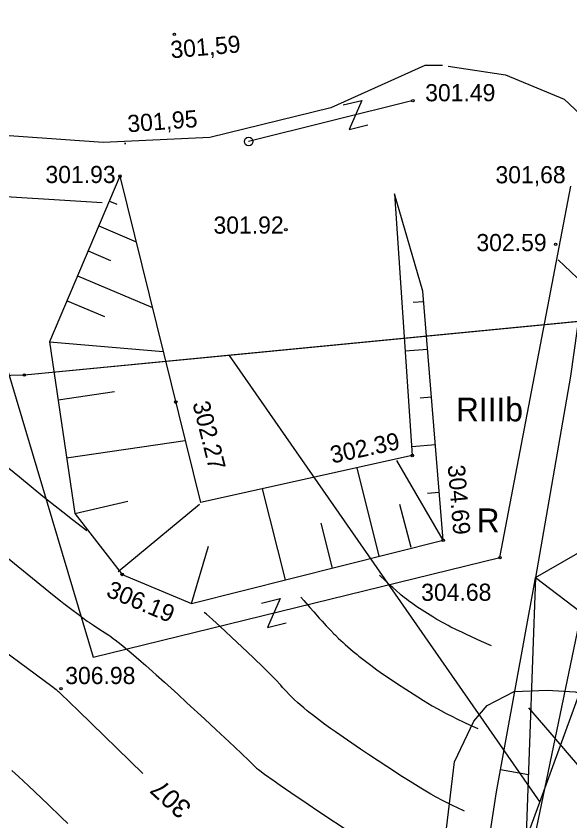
# Model space of a CAD drawing. Extents: x 7477803 to 7478145, y 5500698 to 5500984.
# Drawn here: x 7478004.34 to 7478026.29, y 5500777.55 to 5500809.46 of the extents above; entities that cross this region are included whole.
import ezdxf

# ---------------------------------------------------------------- set-up
doc = ezdxf.new("R2010")
doc.units = 0
for name, color, linetype in [('203-Punkt załamania granicy działki nie stabilizowany', 7, 'Continuous'), ('e_Proj', 7, 'Continuous'), ('gr_dzialki', 7, 'Continuous'), ('gr_klasy', 7, 'Continuous'), ('jezdnia', 7, 'Continuous'), ('kraweznik', 7, 'Continuous'), ('ogr_symb', 7, 'Continuous'), ('ogr_w_skali', 7, 'Continuous'), ('opis_klasy', 7, 'Continuous'), ('opis_uzytek', 7, 'Continuous'), ('pkt_wys', 7, 'Continuous'), ('przehaczenie', 7, 'Continuous'), ('skarp_wypel', 7, 'Continuous'), ('skarpa_gora', 7, 'Continuous'), ('t', 7, 'Continuous'), ('warst_ciagla', 7, 'Continuous'), ('warst_opis', 7, 'Continuous'), ('warst_pogrub', 7, 'Continuous'), ('warst_przeryw', 7, 'Continuous')]:
    doc.layers.add(name, color=color, linetype=linetype)

# ---------------------------------------------------------------- blocks, each defined once
blk = doc.blocks.new('203')
blk.add_circle((0, 0), 0.045)
blk = doc.blocks.new('140')
at = {"layer": 'pkt_wys'}
blk.add_circle((0, 0), 0.045, dxfattribs=at)
blk.add_circle((0, 0), 0.045, dxfattribs=at)
blk = doc.blocks.new('801')
at = {"layer": 'pkt_wys'}
blk.add_circle((0, 0), 0.045, dxfattribs=at)
blk.add_circle((0, 0), 0.045, dxfattribs=at)
blk = doc.blocks.new('POINT_DISPLAY')
blk.add_line((0, 0), (0, 0))
blk = doc.blocks.new('801_5_1')
at = {"layer": 'pkt_wys'}
blk.add_circle((0, 0), 0.05, dxfattribs=at)
blk.add_circle((0, 0), 0.05, dxfattribs=at)
blk = doc.blocks.new('991_5_1')
at = {"layer": 'przehaczenie'}
blk.add_lwpolyline([(-0.38, 0.5), (0.38, 0.5), (-0.38, -0.5), (0.38, -0.5)], dxfattribs=at)
blk = doc.blocks.new('801_5_3')
at = {"layer": 'pkt_wys'}
blk.add_circle((0, 0), 0.05, dxfattribs=at)
blk.add_circle((0, 0), 0.05, dxfattribs=at)

msp = doc.modelspace()

# ---------------------------------------------------------------- linework, layer by layer
at = {"layer": 'e_Proj'}
msp.add_lwpolyline([(7478085.721, 5500828.46), (7478062.59, 5500828.394), (7478057.723, 5500828.457), (7478045.093, 5500816.16), (7478029.949, 5500801.309), (7478024.948, 5500777.245), (7478020.357, 5500757.697), (7478013.921, 5500735.554), (7478010.536, 5500720.256)], dxfattribs=at)
at = {"layer": 'gr_dzialki'}
for points in [[(7478036.02, 5500798.26), (7478004.67, 5500795.23)], [(7478004.67, 5500795.23), (7477980.59, 5500794.64)]]:
    msp.add_lwpolyline(points, dxfattribs=at)
at = {"layer": 'gr_klasy'}
for points in [[(7478030.37, 5500797.71), (7478012.78, 5500796.01)], [(7478012.78, 5500796.01), (7478004.67, 5500795.23)], [(7478012.78, 5500796.01), (7478025.09, 5500778.3)], [(7478004.67, 5500795.23), (7477980.59, 5500794.64)], [(7478025.09, 5500778.3), (7478028.63, 5500788.01)], [(7478019.23, 5500762.35), (7478025.09, 5500778.3)]]:
    msp.add_lwpolyline(points, dxfattribs=at)
at = {"layer": 'jezdnia'}
for points in [[(7478007.787, 5500804.444), (7477996.226, 5500805.272), (7477980.454, 5500806.765), (7477965.783, 5500808.078), (7477950.842, 5500809.092), (7477941.412, 5500809.312), (7477933.642, 5500808.883), (7477925.833, 5500807.985), (7477921.044, 5500806.84), (7477908.409, 5500802.106), (7477902.302, 5500799.559), (7477897.005, 5500796.683), (7477891.579, 5500793.077), (7477886.813, 5500789.372), (7477881.349, 5500784.496), (7477881.326, 5500784.471)], [(7478021.234, 5500807.499), (7478020.534, 5500807.508), (7478016.815, 5500805.824), (7478012.017, 5500804.649), (7478007.787, 5500804.444)]]:
    msp.add_lwpolyline(points, dxfattribs=at)
at = {"layer": 'kraweznik'}
msp.add_lwpolyline([(7478021.467, 5500807.475), (7478023.732, 5500807.128), (7478026.054, 5500806.173), (7478027.956, 5500804.381), (7478029.354, 5500802.427), (7478030.248, 5500801.153), (7478031.021, 5500799.823), (7478031.916, 5500797.559), (7478032.259, 5500795.246), (7478031.695, 5500792.194), (7478036.74, 5500790.972)], dxfattribs=at)
at = {"layer": 'ogr_symb'}
for points in [[(7478020.018, 5500806.096), (7478013.557, 5500804.491)], [(7478023.515, 5500787.992), (7478026.319, 5500802.715)], [(7478003.756, 5500796.28), (7478007.399, 5500784.044), (7478023.515, 5500787.992)]]:
    msp.add_lwpolyline(points, dxfattribs=at)
at = {"layer": 'ogr_w_skali'}
msp.add_circle((7478013.557, 5500804.491), 0.17, dxfattribs=at)
msp.add_circle((7478013.557, 5500804.491), 0.17, dxfattribs=at)
at = {"layer": 'pkt_wys'}
msp.add_lwpolyline([(7478008.633, 5500804.409), (7478008.685, 5500804.407)], dxfattribs=at)
msp.add_lwpolyline([(7478008.633, 5500804.409), (7478008.685, 5500804.407)], dxfattribs=at)
msp.add_arc((7478008.657, 5500804.365), 0.05, 56.1028, 119.1086, dxfattribs=at)
msp.add_arc((7478008.657, 5500804.365), 0.05, 56.1028, 119.1086, dxfattribs=at)
at = {"layer": 'skarp_wypel'}
for p, q in [((7478008.039, 5500802.128), (7478008.334, 5500802.002)), ((7478007.619, 5500801.14), (7478009.101, 5500800.511)), ((7478007.2, 5500800.153), (7478008.086, 5500799.776)), ((7478006.78, 5500799.166), (7478009.743, 5500797.907)), ((7478006.361, 5500798.178), (7478007.838, 5500797.551)), ((7478020.488, 5500798.136), (7478020.074, 5500798.102)), ((7478005.666, 5500796.542), (7478010.174, 5500796.162)), ((7478020.643, 5500796.245), (7478019.761, 5500796.172)), ((7478006.003, 5500794.242), (7478008.243, 5500794.571)), ((7478020.798, 5500794.353), (7478020.357, 5500794.317)), ((7478006.34, 5500791.942), (7478011.044, 5500792.633)), ((7478020.954, 5500792.462), (7478020.017, 5500792.385)), ((7478021.264, 5500788.679), (7478019.429, 5500791.846)), ((7478018.733, 5500788.044), (7478017.853, 5500791.551)), ((7478015.015, 5500787.111), (7478014.109, 5500790.719)), ((7478021.109, 5500790.571), (7478020.639, 5500790.532)), ((7478024.924, 5500787.202), (7478030.818, 5500790.618)), ((7478006.663, 5500789.743), (7478008.775, 5500790.232)), ((7478008.383, 5500787.443), (7478011.606, 5500790.11)), ((7478019.995, 5500788.392), (7478019.546, 5500790.098)), ((7478016.874, 5500787.577), (7478016.428, 5500789.353)), ((7478011.297, 5500786.178), (7478011.961, 5500788.446)), ((7478023.537, 5500779.595), (7478024.639, 5500779.393))]:
    msp.add_line(p, q, dxfattribs=at)
at = {"layer": 'skarpa_gora'}
msp.add_line((7478008.458, 5500803.115), (7478011.651, 5500790.173), dxfattribs=at)
for points in [[(7478007.749, 5500802.055), (7477980.618, 5500803.745), (7477949.546, 5500805.521), (7477933.975, 5500805.774), (7477921.168, 5500803.47), (7477908.381, 5500800.266), (7477897.978, 5500794.654), (7477888.325, 5500787.474), (7477883.93, 5500782.828)], [(7478008.458, 5500803.115), (7478005.666, 5500796.542), (7478006.663, 5500789.743), (7478008.546, 5500787.325), (7478011.297, 5500786.178), (7478021.264, 5500788.679), (7478020.453, 5500798.558), (7478019.339, 5500802.417)], [(7478019.339, 5500802.417), (7478020.04, 5500792.038), (7478011.651, 5500790.173)], [(7478025.82, 5500799.793), (7478026.819, 5500798.852), (7478026.304, 5500795.183), (7478024.924, 5500787.202), (7478034.104, 5500780.215), (7478036.041, 5500775.672), (7478038.759, 5500769.132)], [(7478008.529, 5500720.966), (7478013.614, 5500738.374), (7478016.556, 5500749.806), (7478020.275, 5500763.382), (7478022.118, 5500770.559), (7478023.375, 5500778.71), (7478024.881, 5500786.965)], [(7478024.881, 5500786.965), (7478024.924, 5500787.202), (7478024.325, 5500770.813), (7478019.007, 5500749.589), (7478017.956, 5500746.211), (7478015.629, 5500736.387), (7478013.818, 5500729.802), (7478010.366, 5500720.316)]]:
    msp.add_lwpolyline(points, dxfattribs=at)
at = {"layer": 't'}
msp.add_lwpolyline([(7478013.952, 5500749.22), (7478016.25, 5500756.094), (7478018.043, 5500762.466), (7478020.822, 5500772.519), (7478021.714, 5500779.89), (7478022.482, 5500781.51), (7478023.011, 5500782.131), (7478024.071, 5500782.682), (7478025.381, 5500782.734), (7478026.491, 5500782.665), (7478029.072, 5500781.778), (7478030.398, 5500780.809)], dxfattribs=at)
at = {"layer": 'warst_ciagla'}
for points in [[(7478007.15, 5500789.054), (7478006.579, 5500789.493), (7478006.188, 5500789.799), (7478005.406, 5500790.421), (7478004.472, 5500791.175), (7478003.267, 5500792.155), (7478002.666, 5500792.64), (7478002.125, 5500793.072), (7478001.851, 5500793.289), (7478001.432, 5500793.613), (7478001.005, 5500793.938), (7478000.786, 5500794.101), (7478000.34, 5500794.426), (7478000.112, 5500794.589), (7477999.761, 5500794.833)], [(7478001.984, 5500785.687), (7478004.486, 5500783.837), (7478005.76, 5500782.892), (7478005.923, 5500782.769), (7478005.988, 5500782.716), (7478006.025, 5500782.684), (7478006.105, 5500782.608), (7478006.816, 5500781.917), (7478009.361, 5500779.436)], [(7478022.103, 5500777.945), (7478021.829, 5500778.069), (7478021.663, 5500778.147), (7478021.366, 5500778.292), (7478021.232, 5500778.361), (7478020.989, 5500778.49), (7478020.772, 5500778.613), (7478020.637, 5500778.692), (7478020.38, 5500778.847), (7478019.951, 5500779.115), (7478019.657, 5500779.302), (7478019.031, 5500779.707), (7478018.339, 5500780.163), (7478017.986, 5500780.4), (7478017.472, 5500780.75), (7478017, 5500781.079), (7478016.806, 5500781.218), (7478016.561, 5500781.395), (7478016.445, 5500781.481), (7478016.2, 5500781.666), (7478016.085, 5500781.755), (7478015.94, 5500781.869), (7478015.871, 5500781.924), (7478015.74, 5500782.032), (7478015.58, 5500782.167), (7478015.507, 5500782.232), (7478015.356, 5500782.37), (7478015.289, 5500782.435), (7478015.166, 5500782.559), (7478015.053, 5500782.68), (7478014.904, 5500782.845), (7478014.825, 5500782.931), (7478014.627, 5500783.142), (7478014.317, 5500783.46), (7478014.141, 5500783.634), (7478013.742, 5500784.024), (7478013.506, 5500784.25), (7478013.086, 5500784.646), (7478012.428, 5500785.257), (7478012.123, 5500785.535), (7478011.883, 5500785.748), (7478011.798, 5500785.82)], [(7478024.645, 5500782.041), (7478025.489, 5500781.057), (7478026.336, 5500780.074), (7478027.186, 5500779.094), (7478028.037, 5500778.115)]]:
    msp.add_lwpolyline(points, dxfattribs=at)
at = {"layer": 'warst_pogrub'}
msp.add_lwpolyline([(7478023.182, 5500784.49), (7478022.789, 5500784.667), (7478022.183, 5500784.944), (7478022.027, 5500785.017), (7478021.77, 5500785.141), (7478021.572, 5500785.24), (7478021.465, 5500785.296), (7478021.285, 5500785.394), (7478021.018, 5500785.545), (7478020.853, 5500785.642), (7478020.746, 5500785.706), (7478020.537, 5500785.836), (7478020.327, 5500785.971), (7478020.22, 5500786.043), (7478020.058, 5500786.155), (7478019.892, 5500786.277), (7478019.807, 5500786.342), (7478019.722, 5500786.409), (7478019.606, 5500786.504), (7478019.547, 5500786.554), (7478019.427, 5500786.656), (7478019.265, 5500786.801), (7478019.182, 5500786.877), (7478018.993, 5500787.056), (7478018.746, 5500787.301)], dxfattribs=at)
at = {"layer": 'warst_przeryw'}
for points in [[(7478003.413, 5500788.456), (7478005.133, 5500787.052), (7478005.637, 5500786.645), (7478005.845, 5500786.48), (7478006.107, 5500786.273), (7478006.232, 5500786.175), (7478006.496, 5500785.971), (7478006.85, 5500785.704), (7478006.991, 5500785.6), (7478007.164, 5500785.475), (7478007.244, 5500785.419), (7478007.408, 5500785.308), (7478007.618, 5500785.174), (7478007.875, 5500785.011), (7478008.016, 5500784.915), (7478008.094, 5500784.86), (7478008.206, 5500784.777), (7478008.265, 5500784.732), (7478008.391, 5500784.634), (7478008.574, 5500784.488), (7478008.671, 5500784.408), (7478008.906, 5500784.213), (7478009.297, 5500783.877), (7478009.487, 5500783.712), (7478009.753, 5500783.476), (7478009.893, 5500783.351), (7478010.223, 5500783.055), (7478010.751, 5500782.573), (7478011.112, 5500782.241), (7478011.806, 5500781.599), (7478012.267, 5500781.17), (7478012.788, 5500780.683), (7478013.009, 5500780.476), (7478013.289, 5500780.211), (7478013.569, 5500779.943), (7478013.669, 5500779.845), (7478013.807, 5500779.709), (7478013.869, 5500779.651), (7478013.946, 5500779.588), (7478013.993, 5500779.55), (7478014.186, 5500779.406), (7478014.563, 5500779.138), (7478014.803, 5500778.971), (7478015.227, 5500778.681), (7478015.911, 5500778.218), (7478016.304, 5500777.954), (7478017.624, 5500777.075)], [(7478015.618, 5500786.423), (7478015.739, 5500786.289), (7478015.9, 5500786.108), (7478015.981, 5500786.017), (7478016.139, 5500785.836), (7478016.353, 5500785.591), (7478016.463, 5500785.467), (7478016.632, 5500785.282), (7478016.719, 5500785.189), (7478016.809, 5500785.097), (7478016.931, 5500784.973), (7478016.993, 5500784.912), (7478017.121, 5500784.789), (7478017.297, 5500784.626), (7478017.387, 5500784.544), (7478017.596, 5500784.361), (7478017.704, 5500784.27), (7478017.851, 5500784.149), (7478017.926, 5500784.088), (7478018.078, 5500783.967), (7478018.287, 5500783.806), (7478018.393, 5500783.726), (7478018.64, 5500783.546), (7478018.766, 5500783.456), (7478019.022, 5500783.278), (7478019.28, 5500783.103), (7478019.451, 5500782.989), (7478019.784, 5500782.772), (7478020.255, 5500782.472), (7478020.484, 5500782.33), (7478020.832, 5500782.12), (7478021.051, 5500781.994), (7478021.172, 5500781.926), (7478021.379, 5500781.816), (7478021.629, 5500781.689), (7478021.774, 5500781.618), (7478022.113, 5500781.458), (7478022.309, 5500781.368), (7478022.643, 5500781.218)], [(7478004.179, 5500779.552), (7478004.441, 5500779.309), (7478004.833, 5500778.942), (7478005.354, 5500778.449), (7478005.613, 5500778.2), (7478006.131, 5500777.702), (7478006.391, 5500777.454)]]:
    msp.add_lwpolyline(points, dxfattribs=at)

# ---------------------------------------------------------------- block references
at = {"layer": '203-Punkt załamania granicy działki nie stabilizowany'}
msp.add_blockref('203', (7478004.67, 5500795.23), dxfattribs=at)
at = {"layer": 'pkt_wys', "rotation": 0.0626175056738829}
for name, p in [('801_5_3', (7478010.612, 5500808.737)), ('801_5_1', (7478020.065, 5500806.108)), ('140', (7478025.953, 5500803.385)), ('801_5_1', (7478008.458, 5500803.115)), ('801_5_1', (7478015.031, 5500800.992)), ('801_5_1', (7478025.721, 5500800.414)), ('801_5_1', (7478010.668, 5500794.158)), ('801_5_1', (7478020.04, 5500792.038)), ('801_5_1', (7478021.264, 5500788.679)), ('801_5_1', (7478023.515, 5500787.992)), ('801_5_1', (7478008.546, 5500787.325)), ('801', (7478006.121, 5500782.793))]:
    msp.add_blockref(name, p, dxfattribs=at)
at = {"layer": 'przehaczenie'}
for p, rotation in [((7478017.791, 5500805.543), 13.953808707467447), ((7478014.553, 5500785.796), 13.76385074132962)]:
    msp.add_blockref('991_5_1', p, dxfattribs=dict(at, rotation=rotation))
at = {"layer": 'skarp_wypel'}
msp.add_blockref('POINT_DISPLAY', (7478008.458, 5500803.115), dxfattribs=at)

# ---------------------------------------------------------------- texts
at = {"layer": 'opis_klasy'}
msp.add_text('RIIIb', height=0.94, dxfattribs=at).set_placement((7478021.771, 5500793.395))
at = {"layer": 'opis_uzytek'}
msp.add_text('R', height=0.94, dxfattribs=at).set_placement((7478022.59, 5500789))
at = {"layer": 'pkt_wys'}
for s, rotation, p in [('301,59', 4.9469, (7478010.488, 5500807.785)), ('301.49', 0.0626, (7478020.552, 5500806.082)), ('301,95', 4.3628, (7478008.777, 5500804.851)), ('301.93', 0.0626, (7478005.505, 5500802.84)), ('301,68', 0.0626, (7478023.336, 5500802.831)), ('301.92', 0.0626, (7478012.163, 5500800.835)), ('302.59', 0.0626, (7478022.582, 5500800.141)), ('302.27', 284.0227, (7478011.326, 5500794.106)), ('302.39', 12.0788, (7478016.87, 5500791.72)), ('304.69', 274.6783, (7478021.444, 5500791.646)), ('306.19', 337.3026, (7478007.871, 5500786.472)), ('304.68', 0.0626, (7478020.393, 5500786.277)), ('306.98', 0.0626, (7478006.289, 5500782.977))]:
    msp.add_text(s, height=0.68, rotation=rotation, dxfattribs=at).set_placement(p)
at = {"layer": 'warst_opis'}
msp.add_text('307', height=0.75, rotation=137.6332, dxfattribs=at).set_placement((7478011.339, 5500778.139))

doc.saveas('drawing.dxf')
